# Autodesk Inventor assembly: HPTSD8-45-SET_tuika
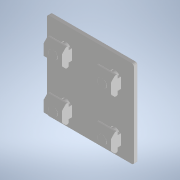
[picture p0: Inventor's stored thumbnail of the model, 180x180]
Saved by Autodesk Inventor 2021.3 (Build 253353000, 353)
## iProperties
Created: 2022-02
Part Number: HPTSD8-45-SET_tuika
Document SubType Name: Assembly
Designer: kengo
Author: kengo
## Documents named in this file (4)
- C:\Users\kengo\Documents\S2S_frame\SDC345\frame_misumi_ver12\HPTSD8-45-SET_tuika.iam
- C:\Users\kengo\Documents\S2S_frame\SDC345\frame_misumi_ver12\HPTSD8-45.ipt
- C:\Users\kengo\Documents\S2S_frame\SDC345\frame_misumi_ver12\HNTT8-8.ipt
- C:\Users\kengo\Documents\S2S_frame\SDC345\frame_misumi_ver12\CBM8-15.ipt
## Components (9 placed, 3 different names)
1. HPTSD8-45
2. HNTT8-8 — フラッシュ:1
3. CBM8-15
4. HNTT8-8:1 — フラッシュ:2
5. CBM8-15:1
6. HNTT8-8:2 — フラッシュ:1
7. CBM8-15:2
8. HNTT8-8:3 — フラッシュ:2
9. CBM8-15:3
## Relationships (2: Flush 2)
- フラッシュ:1 [Flush]: HNTT8-8 ↔ HNTT8-8:2
- フラッシュ:2 [Flush]: HNTT8-8:1 ↔ HNTT8-8:3
